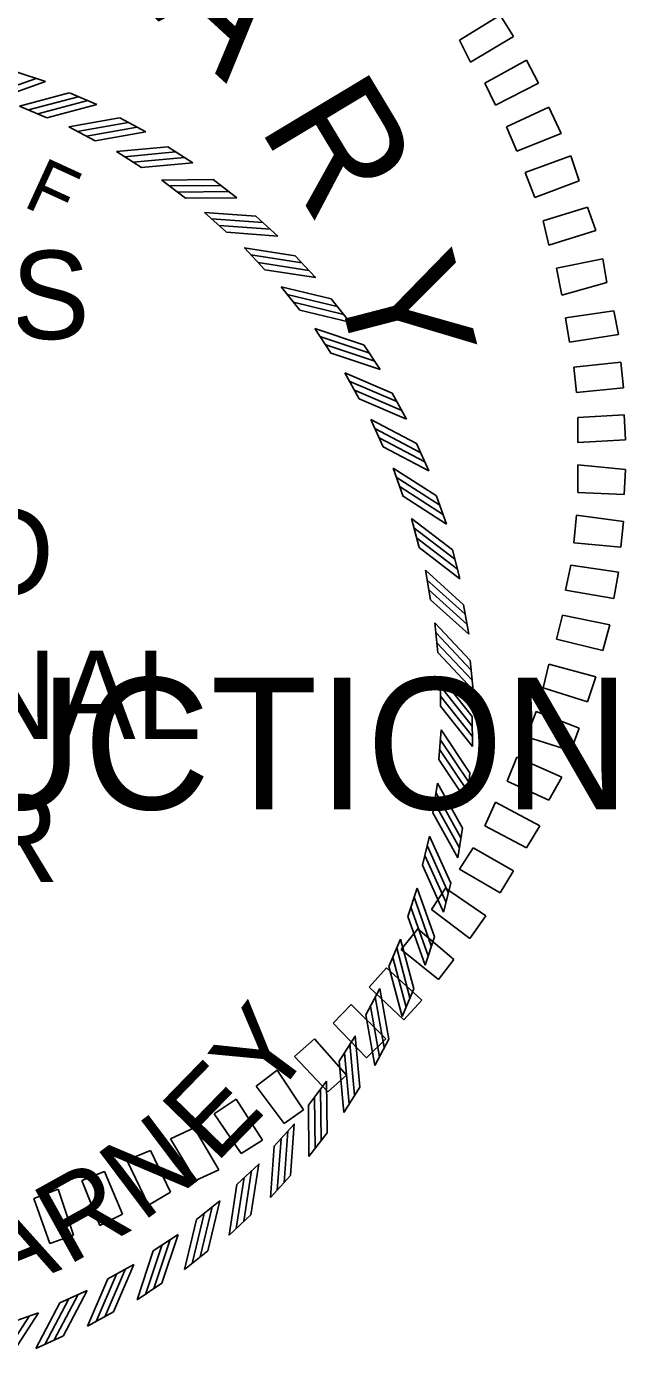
# Model space of a CAD drawing. Extents: x 16 to 1228743, y 11 to 152440.
# Drawn here: x 17.7949 to 17.8708, y 10.8192 to 10.988 of the extents above; entities that cross this region are included whole.
import ezdxf

# ---------------------------------------------------------------- set-up
doc = ezdxf.new("R2010")
doc.units = 0
doc.layers.add('STAMP_JUSTIN', color=7, linetype='Continuous')
doc.layers.add('STAMP_PRELIM', color=7, linetype='Continuous')

msp = doc.modelspace()

# ---------------------------------------------------------------- linework, layer by layer
at = {"layer": 'STAMP_JUSTIN'}
for p, q in [((17.79372, 10.98219), (17.7973, 10.981)), ((17.80033, 10.97957), (17.80379, 10.97809)), ((17.79402, 10.97791), (17.79749, 10.97642)), ((17.8067, 10.97642), (17.81003, 10.97465)), ((17.80027, 10.97528), (17.80361, 10.97351)), ((17.81278, 10.97275), (17.81596, 10.97072)), ((17.80629, 10.97214), (17.80947, 10.97011)), ((17.81202, 10.96852), (17.81502, 10.96623)), ((17.81854, 10.96859), (17.82154, 10.9663)), ((17.81744, 10.96444), (17.82024, 10.96191)), ((17.82394, 10.96397), (17.82674, 10.96144)), ((17.8225, 10.95993), (17.82508, 10.95717)), ((17.82894, 10.95892), (17.83152, 10.95617)), ((17.82717, 10.95501), (17.82952, 10.95205)), ((17.83351, 10.95347), (17.83585, 10.95052)), ((17.83142, 10.94972), (17.83351, 10.94658)), ((17.83761, 10.94767), (17.8397, 10.94453)), ((17.83521, 10.94411), (17.83704, 10.9408)), ((17.84121, 10.94155), (17.84304, 10.93825)), ((17.83853, 10.93819), (17.84008, 10.93475)), ((17.8443, 10.93515), (17.84585, 10.93171)), ((17.84135, 10.93202), (17.84261, 10.92846)), ((17.84685, 10.92851), (17.84811, 10.92496)), ((17.84366, 10.92565), (17.84462, 10.92199)), ((17.84884, 10.92169), (17.8498, 10.91805)), ((17.84542, 10.9191), (17.84608, 10.91538)), ((17.85027, 10.91473), (17.85092, 10.91102)), ((17.84664, 10.91243), (17.84699, 10.90866)), ((17.85111, 10.90767), (17.85146, 10.90392)), ((17.84731, 10.90568), (17.84734, 10.9019)), ((17.85137, 10.90057), (17.8514, 10.8968)), ((17.84741, 10.8989), (17.84714, 10.89513)), ((17.85104, 10.89347), (17.85076, 10.88971)), ((17.84696, 10.89213), (17.84637, 10.8884)), ((17.85012, 10.88642), (17.84954, 10.8827)), ((17.84595, 10.88542), (17.84505, 10.88175)), ((17.84439, 10.87883), (17.84319, 10.87524)), ((17.84863, 10.87948), (17.84774, 10.87581)), ((17.84228, 10.87238), (17.8408, 10.8689)), ((17.84657, 10.87268), (17.84538, 10.8691)), ((17.83966, 10.86613), (17.83789, 10.86279)), ((17.84395, 10.86607), (17.84247, 10.8626)), ((17.83652, 10.86011), (17.83449, 10.85693)), ((17.8408, 10.8597), (17.83903, 10.85637)), ((17.8329, 10.85438), (17.83061, 10.85137)), ((17.83713, 10.85362), (17.83509, 10.85044)), ((17.82882, 10.84896), (17.82629, 10.84616)), ((17.83297, 10.84785), (17.83068, 10.84486)), ((17.82431, 10.8439), (17.82155, 10.84132)), ((17.82835, 10.84245), (17.82582, 10.83966)), ((17.81939, 10.83923), (17.81643, 10.83688)), ((17.8233, 10.83745), (17.82055, 10.83488)), ((17.8141, 10.83498), (17.81096, 10.83289)), ((17.81785, 10.83289), (17.8149, 10.83055)), ((17.80848, 10.83118), (17.80518, 10.82935)), ((17.80257, 10.82786), (17.79912, 10.82631)), ((17.81205, 10.82879), (17.80891, 10.8267)), ((17.7964, 10.82504), (17.79284, 10.82378)), ((17.80592, 10.82518), (17.80262, 10.82336)), ((17.79952, 10.82209), (17.79609, 10.82055))]:
    msp.add_line(p, q, dxfattribs=at)
for points in [[(17.78997, 10.97923), (17.79611, 10.98141)], [(17.79115, 10.97882), (17.7973, 10.981)], [(17.79401, 10.9779), (17.80032, 10.97957)], [(17.79513, 10.97742), (17.80143, 10.97908)], [(17.79634, 10.97693), (17.80265, 10.97859)], [(17.79749, 10.97642), (17.8038, 10.97809)], [(17.80027, 10.97528), (17.80669, 10.97642)], [(17.80133, 10.9747), (17.80776, 10.97584)], [(17.8025, 10.97411), (17.80893, 10.97525)], [(17.80361, 10.97352), (17.81003, 10.97466)], [(17.80628, 10.97214), (17.81278, 10.97275)], [(17.8073, 10.97148), (17.81379, 10.97209)], [(17.80841, 10.9708), (17.81491, 10.9714)], [(17.80947, 10.97011), (17.81596, 10.97072)], [(17.81201, 10.96852), (17.81854, 10.96859)], [(17.81297, 10.96778), (17.81949, 10.96785)], [(17.81403, 10.96701), (17.82055, 10.96707)], [(17.81502, 10.96624), (17.82154, 10.9663)], [(17.81743, 10.96444), (17.82394, 10.96397)], [(17.81832, 10.96362), (17.82483, 10.96315)], [(17.81931, 10.96277), (17.82582, 10.96229)], [(17.82024, 10.96191), (17.82674, 10.96144)], [(17.82249, 10.95993), (17.82894, 10.95892)], [(17.82331, 10.95904), (17.82976, 10.95803)], [(17.82423, 10.9581), (17.83067, 10.95709)], [(17.82508, 10.95718), (17.83153, 10.95617)], [(17.82716, 10.95501), (17.8335, 10.95348)], [(17.82791, 10.95405), (17.83425, 10.95252)], [(17.82874, 10.95305), (17.83508, 10.95151)], [(17.82951, 10.95206), (17.83585, 10.95052)], [(17.83141, 10.94973), (17.8376, 10.94767)], [(17.83207, 10.94871), (17.83826, 10.94666)], [(17.83282, 10.94764), (17.83902, 10.94558)], [(17.83351, 10.94659), (17.8397, 10.94453)], [(17.83521, 10.94411), (17.84121, 10.94155)], [(17.83579, 10.94304), (17.84179, 10.94048)], [(17.83644, 10.94191), (17.84244, 10.93935)], [(17.83704, 10.9408), (17.84304, 10.93825)], [(17.83853, 10.9382), (17.8443, 10.93515)], [(17.83902, 10.93708), (17.84478, 10.93404)], [(17.83958, 10.9359), (17.84535, 10.93286)], [(17.84008, 10.93475), (17.84585, 10.93171)], [(17.84135, 10.93203), (17.84685, 10.92852)], [(17.84174, 10.93088), (17.84724, 10.92737)], [(17.84221, 10.92966), (17.8477, 10.92614)], [(17.84262, 10.92847), (17.84811, 10.92496)], [(17.84365, 10.92565), (17.84884, 10.9217)], [(17.84395, 10.92447), (17.84914, 10.92052)], [(17.84431, 10.92321), (17.8495, 10.91926)], [(17.84462, 10.922), (17.84981, 10.91804)], [(17.84542, 10.9191), (17.85026, 10.91473)], [(17.84562, 10.91791), (17.85046, 10.91354)], [(17.84587, 10.91662), (17.85072, 10.91225)], [(17.84608, 10.91538), (17.85093, 10.91101)], [(17.84664, 10.91243), (17.85111, 10.90768)], [(17.84674, 10.91122), (17.85121, 10.90647)], [(17.84689, 10.90992), (17.85136, 10.90517)], [(17.84699, 10.90867), (17.85146, 10.90392)], [(17.84731, 10.90568), (17.85136, 10.90058)], [(17.84731, 10.90447), (17.85136, 10.89936)], [(17.84735, 10.90316), (17.85141, 10.89805)], [(17.84735, 10.9019), (17.85141, 10.8968)], [(17.84741, 10.8989), (17.85103, 10.89348)], [(17.84724, 10.89638), (17.85087, 10.89096)], [(17.84731, 10.89769), (17.85093, 10.89227)], [(17.84714, 10.89513), (17.85076, 10.88971)], [(17.84696, 10.89214), (17.85012, 10.88643)], [(17.84658, 10.88964), (17.84975, 10.88394)], [(17.84676, 10.89094), (17.84992, 10.88523)], [(17.84638, 10.8884), (17.84954, 10.8827)], [(17.84595, 10.88543), (17.84863, 10.87948)], [(17.84537, 10.88297), (17.84805, 10.87703)], [(17.84565, 10.88425), (17.84833, 10.87831)], [(17.84506, 10.88176), (17.84774, 10.87581)], [(17.84438, 10.87883), (17.84656, 10.87268)], [(17.8436, 10.87643), (17.84578, 10.87028)], [(17.84399, 10.87768), (17.84617, 10.87154)], [(17.8432, 10.87524), (17.84538, 10.8691)], [(17.8418, 10.87127), (17.84346, 10.86496)], [(17.84228, 10.87238), (17.84395, 10.86608)], [(17.84131, 10.87006), (17.84297, 10.86375)], [(17.8408, 10.86891), (17.84247, 10.8626)], [(17.83966, 10.86613), (17.8408, 10.85971)], [(17.83908, 10.86506), (17.84022, 10.85864)], [(17.83789, 10.86279), (17.83903, 10.85637)], [(17.83849, 10.86389), (17.83963, 10.85747)], [(17.83652, 10.86012), (17.83713, 10.85362)], [(17.83518, 10.85798), (17.83578, 10.85149)], [(17.83586, 10.8591), (17.83646, 10.85261)], [(17.83449, 10.85693), (17.83509, 10.85044)], [(17.8329, 10.85438), (17.83297, 10.84786)], [(17.83216, 10.85342), (17.83222, 10.8469)], [(17.83061, 10.85138), (17.83068, 10.84485)], [(17.83139, 10.85237), (17.83145, 10.84584)], [(17.828, 10.84807), (17.82753, 10.84157)], [(17.82882, 10.84897), (17.82835, 10.84246)], [(17.82629, 10.84616), (17.82582, 10.83965)], [(17.82714, 10.84708), (17.82667, 10.84058)], [(17.82341, 10.84308), (17.82241, 10.83664)], [(17.82431, 10.84391), (17.8233, 10.83746)], [(17.82155, 10.84132), (17.82055, 10.83487)], [(17.82248, 10.84217), (17.82147, 10.83572)], [(17.81939, 10.83924), (17.81785, 10.8329)], [(17.81742, 10.83765), (17.81589, 10.83131)], [(17.81843, 10.83849), (17.8169, 10.83215)], [(17.81643, 10.83688), (17.8149, 10.83054)], [(17.81309, 10.83432), (17.81103, 10.82813)], [(17.8141, 10.83499), (17.81205, 10.8288)], [(17.81096, 10.83289), (17.80891, 10.82669)], [(17.81202, 10.83357), (17.80996, 10.82738)], [(17.80742, 10.83061), (17.80486, 10.82461)], [(17.80849, 10.83119), (17.80593, 10.82519)], [(17.80518, 10.82935), (17.80262, 10.82335)], [(17.80629, 10.82995), (17.80373, 10.82395)], [(17.80146, 10.82738), (17.79842, 10.82161)], [(17.80257, 10.82787), (17.79953, 10.8221)], [(17.79913, 10.82631), (17.79608, 10.82054)], [(17.80028, 10.82682), (17.79723, 10.82105)], [(17.79526, 10.82465), (17.79175, 10.81916)], [(17.79641, 10.82505), (17.79289, 10.81955)]]:
    msp.add_lwpolyline(points, dxfattribs=at)
at = {"layer": 'STAMP_PRELIM'}
for p, q in [((17.85489, 10.98942), (17.84976, 10.98624)), ((17.8566, 10.98673), (17.85489, 10.98942)), ((17.84976, 10.98624), (17.85115, 10.98347)), ((17.85115, 10.98347), (17.8566, 10.98673)), ((17.85822, 10.98372), (17.85294, 10.98079)), ((17.85977, 10.98079), (17.85822, 10.98372)), ((17.85294, 10.98079), (17.85432, 10.97802)), ((17.85432, 10.97802), (17.85977, 10.98079)), ((17.86108, 10.97777), (17.85571, 10.97526)), ((17.86262, 10.97444), (17.86108, 10.97777)), ((17.85571, 10.97526), (17.85701, 10.97217)), ((17.85701, 10.97217), (17.86262, 10.97444)), ((17.85806, 10.96947), (17.86384, 10.97159)), ((17.86384, 10.97159), (17.8649, 10.96842)), ((17.85929, 10.96631), (17.85806, 10.96947)), ((17.8649, 10.96842), (17.85929, 10.96631)), ((17.86034, 10.96338), (17.86596, 10.96508)), ((17.86596, 10.96508), (17.86701, 10.96215)), ((17.86108, 10.96028), (17.86034, 10.96338)), ((17.86701, 10.96215), (17.86108, 10.96028)), ((17.86791, 10.95857), (17.86205, 10.95735)), ((17.86205, 10.95735), (17.8627, 10.95394)), ((17.8684, 10.95556), (17.86791, 10.95857)), ((17.8627, 10.95394), (17.8684, 10.95556)), ((17.86929, 10.95198), (17.86319, 10.95108)), ((17.86319, 10.95108), (17.86368, 10.94799)), ((17.86987, 10.94897), (17.86929, 10.95198)), ((17.86368, 10.94799), (17.86987, 10.94897)), ((17.87019, 10.94547), (17.86424, 10.94482)), ((17.87052, 10.94222), (17.87019, 10.94547)), ((17.86424, 10.94482), (17.86457, 10.94164)), ((17.86457, 10.94164), (17.87052, 10.94222)), ((17.86473, 10.93847), (17.87059, 10.9388)), ((17.87059, 10.9388), (17.87076, 10.93562)), ((17.86473, 10.93529), (17.86473, 10.93847)), ((17.87076, 10.93562), (17.86473, 10.93529)), ((17.86473, 10.93245), (17.87076, 10.93188)), ((17.86473, 10.92895), (17.86473, 10.93245)), ((17.87076, 10.93188), (17.87059, 10.92871)), ((17.87059, 10.92871), (17.86473, 10.92895)), ((17.86424, 10.9226), (17.86457, 10.9261)), ((17.86457, 10.9261), (17.87052, 10.92529)), ((17.87052, 10.92529), (17.87019, 10.92204)), ((17.87019, 10.92204), (17.86424, 10.9226)), ((17.86319, 10.91658), (17.86384, 10.91976)), ((17.86384, 10.91976), (17.86987, 10.91886)), ((17.86987, 10.91886), (17.86929, 10.91552)), ((17.86929, 10.91552), (17.86319, 10.91658)), ((17.86205, 10.91039), (17.86278, 10.91341)), ((17.86278, 10.91341), (17.8688, 10.91218)), ((17.8688, 10.91218), (17.86791, 10.90893)), ((17.86791, 10.90893), (17.86205, 10.91039)), ((17.86108, 10.90722), (17.86034, 10.90421)), ((17.86701, 10.9056), (17.86108, 10.90722)), ((17.86596, 10.90242), (17.86701, 10.9056)), ((17.86034, 10.90421), (17.86596, 10.90242)), ((17.85945, 10.9012), (17.85822, 10.89802)), ((17.8649, 10.89909), (17.85945, 10.9012)), ((17.86384, 10.89623), (17.8649, 10.89909)), ((17.85822, 10.89802), (17.86384, 10.89623)), ((17.85701, 10.89542), (17.85578, 10.89241)), ((17.8627, 10.8929), (17.85701, 10.89542)), ((17.85578, 10.89241), (17.86108, 10.88997)), ((17.86108, 10.88997), (17.8627, 10.8929)), ((17.85294, 10.88672), (17.85432, 10.88972)), ((17.85432, 10.88972), (17.85994, 10.88672)), ((17.85822, 10.88395), (17.85294, 10.88672)), ((17.85994, 10.88672), (17.85822, 10.88395)), ((17.85147, 10.88395), (17.84976, 10.88126)), ((17.8566, 10.88102), (17.85147, 10.88395)), ((17.84976, 10.88126), (17.85489, 10.87825)), ((17.85489, 10.87825), (17.8566, 10.88102)), ((17.84618, 10.87614), (17.84797, 10.87882)), ((17.84797, 10.87882), (17.8531, 10.87532)), ((17.85106, 10.87247), (17.84618, 10.87614)), ((17.8531, 10.87532), (17.85106, 10.87247)), ((17.84236, 10.87109), (17.84447, 10.8737)), ((17.84447, 10.8737), (17.84903, 10.86979)), ((17.84708, 10.86726), (17.84236, 10.87109)), ((17.84903, 10.86979), (17.84708, 10.86726)), ((17.84048, 10.86873), (17.83829, 10.86628)), ((17.84496, 10.86466), (17.84048, 10.86873)), ((17.83829, 10.86628), (17.84268, 10.86214)), ((17.84268, 10.86214), (17.84496, 10.86466)), ((17.83601, 10.86409), (17.83373, 10.86173)), ((17.84041, 10.85977), (17.83601, 10.86409)), ((17.83373, 10.86173), (17.83796, 10.85733)), ((17.83137, 10.85977), (17.82885, 10.8575)), ((17.83544, 10.85514), (17.83137, 10.85977)), ((17.83796, 10.85733), (17.84041, 10.85977)), ((17.82885, 10.8575), (17.83308, 10.85302)), ((17.82665, 10.85579), (17.82397, 10.85375)), ((17.82999, 10.85075), (17.82665, 10.85579)), ((17.83308, 10.85302), (17.83544, 10.85514)), ((17.82397, 10.85375), (17.82755, 10.84903)), ((17.82144, 10.85212), (17.81867, 10.85026)), ((17.82478, 10.84692), (17.82144, 10.85212)), ((17.81867, 10.85026), (17.82209, 10.84521)), ((17.82755, 10.84903), (17.82999, 10.85075)), ((17.81615, 10.84847), (17.81314, 10.84708)), ((17.81925, 10.84317), (17.81615, 10.84847)), ((17.81314, 10.84708), (17.81632, 10.84179)), ((17.82209, 10.84521), (17.82478, 10.84692)), ((17.8076, 10.8444), (17.81062, 10.84561)), ((17.81037, 10.8387), (17.8076, 10.8444)), ((17.81062, 10.84561), (17.81314, 10.84033)), ((17.80476, 10.84293), (17.80191, 10.84179)), ((17.80704, 10.83756), (17.80476, 10.84293)), ((17.81632, 10.84179), (17.81925, 10.84317)), ((17.79581, 10.83952), (17.7989, 10.84073)), ((17.7989, 10.84073), (17.80086, 10.83487)), ((17.80191, 10.84179), (17.80419, 10.8361)), ((17.79784, 10.83382), (17.79581, 10.83952)), ((17.81314, 10.84033), (17.81037, 10.8387)), ((17.80419, 10.8361), (17.80704, 10.83756)), ((17.80086, 10.83487), (17.79784, 10.83382))]:
    msp.add_line(p, q, dxfattribs=at)

# ---------------------------------------------------------------- texts
at = {"layer": 'STAMP_JUSTIN'}
for s, height, rotation, p in [('F', 0.00686, 335.3628, (17.79429, 10.96527)), ('Y', 0.01042, 53.4433, (17.82597, 10.85141)), ('E', 0.01042, 45.7825, (17.81882, 10.84382)), ('N', 0.01042, 37.0272, (17.8095, 10.83641)), ('R', 0.01042, 29.0016, (17.80005, 10.83094)), ('A', 0.01042, 21.7056, (17.79088, 10.82715))]:
    msp.add_text(s, height=height, rotation=rotation, dxfattribs=at).set_placement(p)
for s, height, p in [('ARKANSAS', 0.011194, (17.72139, 10.94839)), ('LICENSED', 0.011194, (17.72352, 10.91586)), ('PROFESSIONAL', 0.0111936, (17.7006, 10.89773)), ('ENGINEER', 0.011194, (17.72085, 10.87961))]:
    msp.add_text(s, height=height, dxfattribs=at).set_placement(p)
at = {"layer": 'STAMP_PRELIM'}
for s, rotation, p in [('A', 317.4238, (17.81013, 10.98998)), ('R', 301.0067, (17.82421, 10.97533)), ('Y', 284.5896, (17.83373, 10.9567))]:
    msp.add_text(s, height=0.01542, rotation=rotation, dxfattribs=at).set_placement(p)
msp.add_text('CONSTRUCTION', height=0.0166586, dxfattribs=at).set_placement((17.69196, 10.88883))

doc.saveas('drawing.dxf')
